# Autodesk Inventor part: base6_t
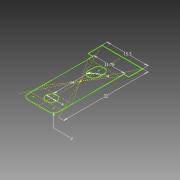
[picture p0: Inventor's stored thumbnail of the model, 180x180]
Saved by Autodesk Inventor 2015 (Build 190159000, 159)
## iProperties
Created: 2017-05
Part Number: base6_t
Material: Generic
Document SubType Name: Modeling
Designer: mcalderon
Density: 1 g/cm^3
Appearance: Default
Author: mcalderon
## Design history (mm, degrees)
sketch "Sketch1" dims "d6" = 4
  geometry: L1 (-3.89, -16)-(3.89, -16); L2 (7.75, 10.65)-(7.75, 16); L3 (7.75, 16)-(-7.75, 16); L4 (-7.75, 16)-(-7.75, 10.65); L5 (-7.75, -16)-(7.75, 16); L6 (7.75, -16)-(-7.75, 16); L7 (5.89, -9.042)-(-5.89, -9.042); L8 (-5.89, -9.042)-(-5.89, 9.042); L9 (-5.89, 9.042)-(5.89, 9.042); L10 (5.89, 9.042)-(5.89, -9.042); L11 (5.89, -9.042)-(-5.89, 9.042); L12 (-5.89, -9.042)-(5.89, 9.042); L13 (5.89, 10.65)-(5.89, -14); L14 (-5.89, 10.65)-(-5.89, -14); L15 (-7.75, 10.65)-(-5.89, 10.65); L16 (5.89, 10.65)-(7.75, 10.65); L17 (0, 16)-(0, -16); L18 (-5.89, -13)-(5.89, -13); L19 (0, -9)-(0, 5); L20 (-2, 7)-(-2, 5); L21 (2, 7)-(2, 5); A1 r 2 centre (3.89, -14) between (3.89, -16) and (5.89, -14); A2 r 2 centre (-3.89, -14) between (-5.89, -14) and (-3.89, -16); A3 r 2 centre (0, 5) between (-2, 5) and (2, 5); A4 r 2 centre (0, 7) between (2, 7) and (-2, 7); 2 further points
  constraints: 42 end point, 8 point on circle, 6 midpoint, 6 perpendicular, 6 tangent, 5 point on line, 4 centre point, 4 horizontal, 4 parallel, 2 vertical, 1 coincident, 1 equal radius, 1 vertical alignment, 2 other
  dimensions: "d0" = 15.5 distance of L3.end L2.end; "d1" = 32 distance of L2.end L6.start; "d3" = 11.78 distance of L8.end L9.end; "d4" = 2 radius of A1; "d7" = 14 distance of L19.start L19.end; "d8" = 4 diameter of A3
other parameters: "d2" = 5.35, "d9" = 4
